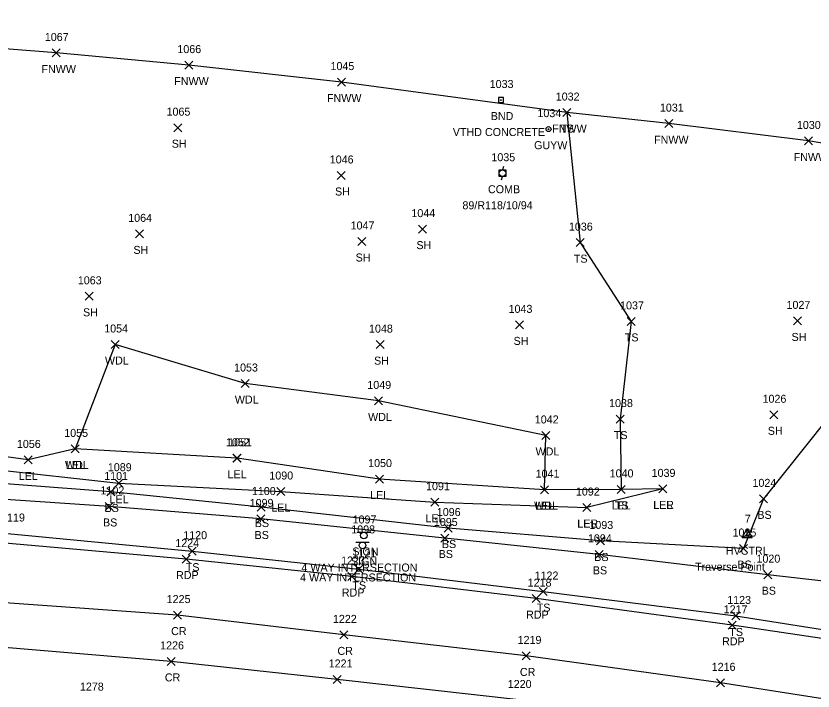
# Model space of a CAD drawing. Extents: x 1629176 to 1637209, y 606063 to 610167.
# Drawn here: x 1629364 to 1629563.1, y 607047.2 to 607215.9 of the extents above; entities that cross this region are included whole.
import ezdxf

# ---------------------------------------------------------------- set-up
doc = ezdxf.new("R2010")
doc.units = 0
for name, color, linetype in [('C_A', 7, 'Continuous'), ('C_C', 7, 'Continuous'), ('C_I', 7, 'Continuous'), ('CPSM', 7, 'Continuous'), ('L_A', 7, 'Continuous'), ('L_I', 7, 'Continuous'), ('L_TIC', 7, 'Continuous'), ('LARO', 7, 'Continuous'), ('LAWA', 7, 'Continuous'), ('LELB', 7, 'Continuous'), ('LFNC', 7, 'Continuous'), ('M_A', 7, 'Continuous'), ('M_C', 7, 'Continuous'), ('M_I', 7, 'Continuous'), ('MHBP', 7, 'Continuous'), ('P_A', 7, 'Continuous'), ('P_I', 7, 'Continuous'), ('P_TIC', 7, 'Continuous'), ('PET', 7, 'Continuous'), ('PRC', 7, 'Continuous'), ('S_A', 7, 'Continuous'), ('S_C', 7, 'Continuous'), ('S_I', 7, 'Continuous'), ('SSGN', 7, 'Continuous'), ('U_A', 7, 'Continuous'), ('U_C', 7, 'Continuous'), ('U_I', 7, 'Continuous'), ('UP', 7, 'Continuous'), ('UPGW', 7, 'Continuous')]:
    doc.layers.add(name, color=color, linetype=linetype)

msp = doc.modelspace()

# ---------------------------------------------------------------- linework, layer by layer
at = {"layer": 'CPSM'}
for p, q in [((1629545.35, 607085.58), (1629546.6, 607087.75)), ((1629545.35, 607085.58), (1629546.6, 607086.3)), ((1629547.85, 607085.58), (1629546.6, 607087.75)), ((1629546.6, 607086.3), (1629546.6, 607087.75)), ((1629546.6, 607086.3), (1629546.6, 607086.3)), ((1629546.6, 607086.3), (1629547.85, 607085.58)), ((1629545.35, 607085.58), (1629547.85, 607085.58))]:
    msp.add_line(p, q, dxfattribs=at)
at = {"layer": 'L_TIC'}
for points in [[(1629373.06, 607205.64), (1629375.06, 607207.64)], [(1629375.06, 607205.64), (1629373.06, 607207.64)], [(1629406.21, 607202.61), (1629408.21, 607204.61)], [(1629408.21, 607202.61), (1629406.21, 607204.61)], [(1629444.35, 607198.37), (1629446.35, 607200.37)], [(1629446.35, 607198.37), (1629444.35, 607200.37)], [(1629500.6, 607190.75), (1629502.6, 607192.75)], [(1629502.6, 607190.75), (1629500.6, 607192.75)], [(1629500.6, 607190.75), (1629502.6, 607192.75)], [(1629502.6, 607190.75), (1629500.6, 607192.75)], [(1629526.04, 607187.99), (1629528.04, 607189.99)], [(1629528.04, 607187.99), (1629526.04, 607189.99)], [(1629403.46, 607186.98), (1629405.46, 607188.98)], [(1629405.46, 607186.98), (1629403.46, 607188.98)], [(1629560.91, 607183.66), (1629562.91, 607185.66)], [(1629562.91, 607183.66), (1629560.91, 607185.66)], [(1629444.22, 607175.04), (1629446.22, 607177.04)], [(1629446.22, 607175.04), (1629444.22, 607177.04)], [(1629393.88, 607160.45), (1629395.88, 607162.45)], [(1629395.88, 607160.45), (1629393.88, 607162.45)], [(1629464.56, 607161.64), (1629466.56, 607163.64)], [(1629466.56, 607161.64), (1629464.56, 607163.64)], [(1629449.37, 607158.55), (1629451.37, 607160.55)], [(1629451.37, 607158.55), (1629449.37, 607160.55)], [(1629503.94, 607158.27), (1629505.94, 607160.27)], [(1629505.94, 607158.27), (1629503.94, 607160.27)], [(1629381.3, 607144.86), (1629383.3, 607146.86)], [(1629383.3, 607144.86), (1629381.3, 607146.86)], [(1629516.67, 607138.59), (1629518.67, 607140.59)], [(1629518.67, 607138.59), (1629516.67, 607140.59)], [(1629558.23, 607138.71), (1629560.23, 607140.71)], [(1629560.23, 607138.71), (1629558.23, 607140.71)], [(1629488.82, 607137.72), (1629490.82, 607139.72)], [(1629490.82, 607137.72), (1629488.82, 607139.72)], [(1629387.84, 607132.82), (1629389.84, 607134.82)], [(1629389.84, 607132.82), (1629387.84, 607134.82)], [(1629453.97, 607132.79), (1629455.97, 607134.79)], [(1629455.97, 607132.79), (1629453.97, 607134.79)], [(1629420.28, 607123.07), (1629422.28, 607125.07)], [(1629422.28, 607123.07), (1629420.28, 607125.07)], [(1629453.55, 607118.72), (1629455.55, 607120.72)], [(1629455.55, 607118.72), (1629453.55, 607120.72)], [(1629513.92, 607114.19), (1629515.92, 607116.19)], [(1629515.92, 607114.19), (1629513.92, 607116.19)], [(1629552.3, 607115.26), (1629554.3, 607117.26)], [(1629554.3, 607115.26), (1629552.3, 607117.26)], [(1629495.37, 607110.1), (1629497.37, 607112.1)], [(1629497.37, 607110.1), (1629495.37, 607112.1)], [(1629377.86, 607106.73), (1629379.86, 607108.73)], [(1629379.86, 607106.73), (1629377.86, 607108.73)], [(1629377.86, 607106.73), (1629379.86, 607108.73)], [(1629379.86, 607106.73), (1629377.86, 607108.73)], [(1629366.09, 607103.98), (1629368.09, 607105.98)], [(1629368.09, 607103.98), (1629366.09, 607105.98)], [(1629418.23, 607104.4), (1629420.23, 607106.4)], [(1629420.23, 607104.4), (1629418.23, 607106.4)], [(1629418.24, 607104.4), (1629420.24, 607106.4)], [(1629420.24, 607104.4), (1629418.24, 607106.4)], [(1629388.76, 607098.17), (1629390.76, 607100.17)], [(1629390.76, 607098.17), (1629388.76, 607100.17)], [(1629453.84, 607099.2), (1629455.84, 607101.2)], [(1629455.84, 607099.2), (1629453.84, 607101.2)], [(1629429.17, 607096.09), (1629431.17, 607098.09)], [(1629431.17, 607096.09), (1629429.17, 607098.09)], [(1629495.01, 607096.55), (1629497.01, 607098.55)], [(1629497.01, 607096.55), (1629495.01, 607098.55)], [(1629495.01, 607096.55), (1629497.01, 607098.55)], [(1629497.01, 607096.55), (1629495.01, 607098.55)], [(1629514.16, 607096.62), (1629516.16, 607098.62)], [(1629516.16, 607096.62), (1629514.16, 607098.62)], [(1629514.16, 607096.62), (1629516.16, 607098.62)], [(1629516.16, 607096.62), (1629514.16, 607098.62)], [(1629524.56, 607096.75), (1629526.56, 607098.75)], [(1629526.56, 607096.75), (1629524.56, 607098.75)], [(1629524.56, 607096.75), (1629526.56, 607098.75)], [(1629526.56, 607096.75), (1629524.56, 607098.75)], [(1629386.71, 607095.98), (1629388.71, 607097.98)], [(1629388.71, 607095.98), (1629386.71, 607097.98)], [(1629549.74, 607094.26), (1629551.74, 607096.26)], [(1629551.74, 607094.26), (1629549.74, 607096.26)], [(1629386.34, 607092.37), (1629388.34, 607094.37)], [(1629388.34, 607092.37), (1629386.34, 607094.37)], [(1629424.24, 607092.21), (1629426.24, 607094.21)], [(1629426.24, 607092.21), (1629424.24, 607094.21)], [(1629467.65, 607093.42), (1629469.65, 607095.42)], [(1629469.65, 607093.42), (1629467.65, 607095.42)], [(1629505.63, 607092.09), (1629507.63, 607094.09)], [(1629507.63, 607092.09), (1629505.63, 607094.09)], [(1629505.63, 607092.09), (1629507.63, 607094.09)], [(1629507.63, 607092.09), (1629505.63, 607094.09)], [(1629424.18, 607089.24), (1629426.18, 607091.24)], [(1629426.18, 607089.24), (1629424.18, 607091.24)], [(1629470.96, 607086.97), (1629472.96, 607088.97)], [(1629472.96, 607086.97), (1629470.96, 607088.97)], [(1629470.16, 607084.48), (1629472.16, 607086.48)], [(1629472.16, 607084.48), (1629470.16, 607086.48)], [(1629509.01, 607083.74), (1629511.01, 607085.74)], [(1629511.01, 607083.74), (1629509.01, 607085.74)], [(1629407.03, 607081.19), (1629409.03, 607083.19)], [(1629409.03, 607081.19), (1629407.03, 607083.19)], [(1629508.64, 607080.4), (1629510.64, 607082.4)], [(1629510.64, 607080.4), (1629508.64, 607082.4)], [(1629544.75, 607081.85), (1629546.75, 607083.85)], [(1629546.75, 607081.85), (1629544.75, 607083.85)], [(1629448.64, 607076.67), (1629450.64, 607078.67)], [(1629450.64, 607076.67), (1629448.64, 607078.67)], [(1629550.82, 607075.32), (1629552.82, 607077.32)], [(1629552.82, 607075.32), (1629550.82, 607077.32)], [(1629494.68, 607071.1), (1629496.68, 607073.1)], [(1629496.68, 607071.1), (1629494.68, 607073.1)], [(1629542.77, 607065.01), (1629544.77, 607067.01)], [(1629544.77, 607065.01), (1629542.77, 607067.01)]]:
    msp.add_lwpolyline(points, dxfattribs=at)
at = {"layer": 'LARO'}
for points in [[(1629525.56, 607097.75), (1629515.16, 607097.62), (1629496.01, 607097.55), (1629454.84, 607100.2), (1629419.24, 607105.4), (1629419.23, 607105.4), (1629378.86, 607107.73), (1629367.09, 607104.98), (1629352.35, 607107.03), (1629331.53, 607114.27), (1629312.1, 607112.36), (1629284.4, 607117.27), (1629264.96, 607112.44), (1629237.03, 607114.71), (1629236.02, 607111.12), (1629264.43, 607110.11), (1629291.77, 607108.71), (1629324.64, 607106.29), (1629358.13, 607102.7), (1629389.76, 607099.17), (1629430.17, 607097.09), (1629468.65, 607094.42), (1629506.63, 607093.09)], [(1629525.56, 607097.75), (1629506.63, 607093.09)]]:
    msp.add_lwpolyline(points, dxfattribs=at)
at = {"layer": 'LAWA'}
msp.add_lwpolyline([(1629496.01, 607097.55), (1629496.37, 607111.1), (1629454.55, 607119.72), (1629421.28, 607124.07), (1629388.84, 607133.82), (1629378.86, 607107.73)], dxfattribs=at)
at = {"layer": 'LELB'}
for points in [[(1629501.6, 607191.75), (1629504.94, 607159.27), (1629517.67, 607139.59), (1629514.92, 607115.19), (1629515.16, 607097.62)], [(1629624.92, 607174.61), (1629622.69, 607143.68), (1629611.35, 607114.32), (1629581.53, 607116.51), (1629566.42, 607115.03), (1629550.74, 607095.26), (1629545.75, 607082.85), (1629510.01, 607084.74), (1629471.96, 607087.97), (1629425.24, 607093.21), (1629387.71, 607096.98), (1629341.68, 607100.48), (1629296.79, 607103.99), (1629252.13, 607105.67), (1629240.26, 607107.21), (1629209.02, 607107.58), (1629183.53, 607109.94)], [(1629683.15, 607057.43), (1629646, 607061.54), (1629600.81, 607070.68), (1629551.82, 607076.32), (1629509.64, 607081.4), (1629471.16, 607085.48), (1629425.18, 607090.24), (1629387.34, 607093.37), (1629341.71, 607096.43), (1629295.02, 607099.94), (1629251.22, 607103.28), (1629239.88, 607103.86), (1629208.74, 607106), (1629183.2, 607107.98)], [(1629182.81, 607095.71), (1629228.31, 607094.18), (1629271.2, 607092.37), (1629318.24, 607089.8), (1629361.89, 607086.6), (1629408.03, 607082.19), (1629449.64, 607077.67), (1629495.68, 607072.1), (1629543.77, 607066.01), (1629589.78, 607058.79)]]:
    msp.add_lwpolyline(points, dxfattribs=at)
at = {"layer": 'LFNC'}
msp.add_lwpolyline([(1629584.57, 607180.8), (1629561.91, 607184.66), (1629527.04, 607188.99), (1629501.6, 607191.75), (1629445.35, 607199.37), (1629407.21, 607203.61), (1629374.06, 607206.64), (1629338.82, 607209.46), (1629316.51, 607210.37), (1629282.73, 607212.04), (1629269.2, 607213.11), (1629248.99, 607214.08), (1629210.8, 607215.89), (1629190.17, 607214.66)], dxfattribs=at)
at = {"layer": 'MHBP'}
for p, q in [((1629485.76, 607195.54), (1629484.51, 607195.54)), ((1629484.51, 607195.54), (1629484.51, 607194.29)), ((1629485.76, 607195.54), (1629484.51, 607195.54)), ((1629484.51, 607195.54), (1629484.51, 607194.29)), ((1629485.76, 607194.29), (1629485.76, 607195.54)), ((1629485.76, 607194.29), (1629485.76, 607195.54)), ((1629484.51, 607194.29), (1629485.76, 607194.29)), ((1629484.51, 607194.29), (1629485.76, 607194.29))]:
    msp.add_line(p, q, dxfattribs=at)
msp.add_circle((1629485.11, 607194.88), 0.0833, dxfattribs=at)
at = {"layer": 'P_TIC'}
for points in [[(1629405.53, 607079.22), (1629407.53, 607081.22)], [(1629407.53, 607079.22), (1629405.53, 607081.22)], [(1629446.94, 607074.86), (1629448.94, 607076.86)], [(1629448.94, 607074.86), (1629446.94, 607076.86)], [(1629492.94, 607069.34), (1629494.94, 607071.34)], [(1629494.94, 607069.34), (1629492.94, 607071.34)], [(1629403.36, 607065.23), (1629405.36, 607067.23)], [(1629405.36, 607065.23), (1629403.36, 607067.23)], [(1629541.89, 607062.67), (1629543.89, 607064.67)], [(1629543.89, 607062.67), (1629541.89, 607064.67)], [(1629444.88, 607060.28), (1629446.88, 607062.28)], [(1629446.88, 607060.28), (1629444.88, 607062.28)], [(1629490.45, 607055.02), (1629492.45, 607057.02)], [(1629492.45, 607055.02), (1629490.45, 607057.02)], [(1629401.79, 607053.66), (1629403.79, 607055.66)], [(1629403.79, 607053.66), (1629401.79, 607055.66)], [(1629443.26, 607049.14), (1629445.26, 607051.14)], [(1629445.26, 607049.14), (1629443.26, 607051.14)], [(1629538.96, 607048.3), (1629540.96, 607050.3)], [(1629540.96, 607048.3), (1629538.96, 607050.3)]]:
    msp.add_lwpolyline(points, dxfattribs=at)
at = {"layer": 'PET'}
msp.add_lwpolyline([(1630115.59, 606918.47), (1630070.26, 606934.37), (1630047.19, 606942.61), (1630027.81, 606949.5), (1629999.64, 606958.79), (1629963.88, 606969.73), (1629916.37, 606983.66), (1629883.8, 606991.87), (1629841.7, 607003.38), (1629794.53, 607014.94), (1629751.13, 607024.85), (1629703.98, 607035.26), (1629666.74, 607043.02), (1629621.43, 607051.04), (1629588.28, 607056.93), (1629542.89, 607063.67), (1629493.94, 607070.34), (1629447.94, 607075.86), (1629406.53, 607080.22), (1629360.37, 607084.28), (1629316.73, 607087.48), (1629269.81, 607090.12), (1629227.29, 607092.24), (1629182.92, 607093.47)], dxfattribs=at)
at = {"layer": 'PRC'}
for points in [[(1630110.18, 606905.77), (1630065.36, 606921.68), (1630022.36, 606935.68), (1629994.71, 606945.36), (1629959.54, 606955.86), (1629913.54, 606969.37), (1629877.41, 606979.26), (1629837.69, 606989.99), (1629791.63, 607000.82), (1629746.42, 607011.44), (1629699.59, 607021.37), (1629664.04, 607028.34), (1629619.43, 607036.79), (1629585.72, 607042.18), (1629539.96, 607049.3), (1629491.45, 607056.02), (1629445.88, 607061.28), (1629404.36, 607066.23), (1629358.89, 607069.49), (1629314.63, 607073.29), (1629269.37, 607075.36), (1629226.58, 607077.32), (1629182.35, 607078.58)], [(1630105.99, 606894.95), (1630061.18, 606910.94), (1630017.61, 606925.74), (1629991.01, 606934.32), (1629955.3, 606944.84), (1629910.77, 606959.12), (1629874.52, 606969.06), (1629834.93, 606979.4), (1629788.74, 606990.13), (1629743.3, 607000.68), (1629697.98, 607010.33), (1629662.17, 607017.56), (1629618.2, 607025.81), (1629583.59, 607031.56), (1629540.4, 607037.95), (1629489.63, 607045.02), (1629444.26, 607050.14), (1629402.79, 607054.66), (1629359.1, 607058.26), (1629313.06, 607061.88), (1629268.47, 607063.97), (1629226.23, 607065.89), (1629182.22, 607066.96)]]:
    msp.add_lwpolyline(points, dxfattribs=at)
at = {"layer": 'SSGN'}
for p, q in [((1629449.24, 607086.97), (1629452.58, 607086.97)), ((1629450.89, 607086.13), (1629450.89, 607086.13)), ((1629448.92, 607084.48), (1629452.25, 607084.48)), ((1629450.56, 607083.65), (1629450.56, 607083.65))]:
    msp.add_line(p, q, dxfattribs=at)
for centre in [(1629450.89, 607086.13), (1629450.56, 607083.65)]:
    msp.add_circle(centre, 0.833, dxfattribs=at)
at = {"layer": 'UP'}
for p, q in [((1629485.78, 607178.27), (1629485.53, 607177.43)), ((1629484.69, 607175.77), (1629484.69, 607177.43)), ((1629484.69, 607177.43), (1629486.36, 607177.43)), ((1629486.36, 607175.77), (1629484.69, 607175.77)), ((1629485.28, 607174.93), (1629485.53, 607175.77)), ((1629485.53, 607176.6), (1629485.53, 607176.6)), ((1629486.36, 607177.43), (1629486.36, 607175.77))]:
    msp.add_line(p, q, dxfattribs=at)
msp.add_circle((1629485.53, 607176.6), 0.833, dxfattribs=at)
at = {"layer": 'UPGW'}
for radius in [0.625, 0.0833]:
    msp.add_circle((1629497.03, 607187.61), radius, dxfattribs=at)

# ---------------------------------------------------------------- texts
at = {"layer": 'C_A'}
msp.add_text('HVCTRL', height=2, dxfattribs=at).set_placement((1629541.3, 607081.3))
at = {"layer": 'C_C'}
msp.add_text('Traverse Point', height=2, dxfattribs=at).set_placement((1629533.65, 607077.3))
at = {"layer": 'C_I'}
msp.add_text('7', height=2, dxfattribs=at).set_placement((1629546.04, 607089.3))
at = {"layer": 'L_A'}
for s, p in [('FNWW', (1629370.41, 607201.64)), ('FNWW', (1629403.56, 607198.61)), ('FNWW', (1629441.7, 607194.37)), ('FNWW', (1629497.95, 607186.75)), ('TS', (1629500.01, 607186.75)), ('FNWW', (1629523.39, 607183.99)), ('SH', (1629402.95, 607182.98)), ('FNWW', (1629558.25, 607179.66)), ('SH', (1629443.71, 607171.04)), ('SH', (1629393.37, 607156.45)), ('SH', (1629464.04, 607157.64)), ('SH', (1629448.86, 607154.55)), ('TS', (1629503.35, 607154.27)), ('SH', (1629380.78, 607140.86)), ('TS', (1629516.08, 607134.59)), ('SH', (1629557.72, 607134.71)), ('SH', (1629488.31, 607133.72)), ('WDL', (1629386.26, 607128.82)), ('SH', (1629453.46, 607128.79)), ('WDL', (1629418.69, 607119.07)), ('WDL', (1629451.97, 607114.72)), ('TS', (1629513.33, 607110.19)), ('SH', (1629551.79, 607111.26)), ('WDL', (1629493.79, 607106.1)), ('WDL', (1629376.27, 607102.73)), ('LEL', (1629376.5, 607102.73)), ('LEL', (1629364.73, 607099.98)), ('LEL', (1629416.87, 607100.4)), ('LEL', (1629416.88, 607100.4)), ('LEL', (1629387.4, 607094.17)), ('LEL', (1629452.47, 607095.2)), ('LEL', (1629427.8, 607092.09)), ('WDL', (1629493.43, 607092.55)), ('LEL', (1629493.65, 607092.55)), ('LEL', (1629512.8, 607092.62)), ('TS', (1629513.57, 607092.62)), ('LER', (1629523.14, 607092.75)), ('LEL', (1629523.2, 607092.75)), ('BS', (1629386.15, 607091.98)), ('BS', (1629549.18, 607090.26)), ('BS', (1629385.78, 607088.37)), ('BS', (1629423.68, 607088.21)), ('LEL', (1629466.29, 607089.42)), ('LER', (1629504.21, 607088.09)), ('LEL', (1629504.27, 607088.09)), ('BS', (1629423.63, 607085.24)), ('BS', (1629470.4, 607082.97)), ('BS', (1629469.6, 607080.48)), ('BS', (1629508.45, 607079.74)), ('TS', (1629406.44, 607077.19)), ('BS', (1629508.09, 607076.4)), ('BS', (1629544.2, 607077.85)), ('TS', (1629448.05, 607072.67)), ('BS', (1629550.26, 607071.32)), ('TS', (1629494.09, 607067.1)), ('TS', (1629542.18, 607061.01))]:
    msp.add_text(s, height=2, dxfattribs=at).set_placement(p)
at = {"layer": 'L_I'}
for s, p in [('1067', (1629371.24, 607209.64)), ('1066', (1629404.34, 607206.61)), ('1045', (1629442.58, 607202.37)), ('1032', (1629498.83, 607194.75)), ('1032', (1629498.83, 607194.75)), ('1031', (1629524.84, 607191.99)), ('1065', (1629401.64, 607190.98)), ('1030', (1629559.05, 607187.66)), ('1046', (1629442.4, 607179.04)), ('1044', (1629462.78, 607165.64)), ('1064', (1629392.07, 607164.45)), ('1047', (1629447.6, 607162.55)), ('1036', (1629502.12, 607162.27)), ('1063', (1629379.48, 607148.86)), ('1037', (1629514.9, 607142.59)), ('1027', (1629556.46, 607142.71)), ('1043', (1629487.05, 607141.72)), ('1054', (1629386.07, 607136.82)), ('1048', (1629452.2, 607136.79)), ('1053', (1629418.51, 607127.07)), ('1049', (1629451.78, 607122.72)), ('1038', (1629512.15, 607118.19)), ('1026', (1629550.47, 607119.26)), ('1042', (1629493.6, 607114.1)), ('1055', (1629376.09, 607110.73)), ('1055', (1629376.09, 607110.73)), ('1056', (1629364.27, 607107.98)), ('1052', (1629416.46, 607108.4)), ('1051', (1629417.03, 607108.4)), ('1089', (1629386.98, 607102.17)), ('1050', (1629451.98, 607103.2)), ('1101', (1629386.07, 607099.98)), ('1090', (1629427.31, 607100.09)), ('1041', (1629493.81, 607100.55)), ('1041', (1629493.81, 607100.55)), ('1040', (1629512.3, 607100.62)), ('1040', (1629512.3, 607100.62)), ('1039', (1629522.78, 607100.75)), ('1039', (1629522.78, 607100.75)), ('1024', (1629547.96, 607098.26)), ('1102', (1629385.14, 607096.37)), ('1100', (1629422.95, 607096.21)), ('1091', (1629466.44, 607097.42)), ('1092', (1629503.86, 607096.09)), ('1092', (1629503.86, 607096.09)), ('1099', (1629422.4, 607093.24)), ('1096', (1629469.13, 607090.97)), ('1119', (1629360.32, 607089.6)), ('1095', (1629468.39, 607088.48)), ('1093', (1629507.23, 607087.74)), ('1120', (1629405.81, 607085.19)), ('1094', (1629506.87, 607084.4)), ('1025', (1629542.98, 607085.85)), ('1121', (1629448.08, 607080.67)), ('1020', (1629548.96, 607079.32)), ('1122', (1629493.55, 607075.1)), ('1123', (1629541.65, 607069.01))]:
    msp.add_text(s, height=2, dxfattribs=at).set_placement(p)
at = {"layer": 'M_A'}
msp.add_text('BND', height=2, dxfattribs=at).set_placement((1629482.6, 607189.89))
at = {"layer": 'M_C'}
msp.add_text('VTHD CONCRETE', height=2, dxfattribs=at).set_placement((1629473.13, 607185.89))
at = {"layer": 'M_I'}
msp.add_text('1033', height=2, dxfattribs=at).set_placement((1629482.34, 607197.89))
at = {"layer": 'P_A'}
for s, p in [('RDP', (1629404.01, 607075.22)), ('RDP', (1629445.42, 607070.86)), ('RDP', (1629491.43, 607065.34)), ('CR', (1629402.79, 607061.23)), ('RDP', (1629540.38, 607058.67)), ('CR', (1629444.32, 607056.28)), ('CR', (1629489.88, 607051.02)), ('CR', (1629401.22, 607049.66))]:
    msp.add_text(s, height=2, dxfattribs=at).set_placement(p)
at = {"layer": 'P_I'}
for s, p in [('1224', (1629403.83, 607083.22)), ('1223', (1629445.24, 607078.86)), ('1218', (1629491.82, 607073.34)), ('1225', (1629401.67, 607069.23)), ('1217', (1629540.76, 607066.67)), ('1222', (1629443.19, 607064.28)), ('1219', (1629489.31, 607059.02)), ('1226', (1629400.04, 607057.66)), ('1221', (1629442.13, 607053.14)), ('1216', (1629537.78, 607052.3)), ('1278', (1629380.01, 607047.36)), ('1220', (1629486.85, 607048.02))]:
    msp.add_text(s, height=2, dxfattribs=at).set_placement(p)
at = {"layer": 'S_A'}
for p in [(1629448.03, 607081.11), (1629447.7, 607078.63)]:
    msp.add_text('SIGN', height=2, dxfattribs=at).set_placement(p)
at = {"layer": 'S_C'}
for p in [(1629435.32, 607077.11), (1629434.99, 607074.63)]:
    msp.add_text('4 WAY INTERSECTION', height=2, dxfattribs=at).set_placement(p)
at = {"layer": 'S_I'}
for s, p in [('1097', (1629448.1, 607089.11)), ('1098', (1629447.77, 607086.63))]:
    msp.add_text(s, height=2, dxfattribs=at).set_placement(p)
at = {"layer": 'U_A'}
for s, p in [('GUYW', (1629493.42, 607182.61)), ('COMB', (1629481.91, 607171.6))]:
    msp.add_text(s, height=2, dxfattribs=at).set_placement(p)
at = {"layer": 'U_C'}
msp.add_text('89/R118/10/94', height=2, dxfattribs=at).set_placement((1629475.53, 607167.6))
at = {"layer": 'U_I'}
for s, p in [('1034', (1629494.26, 607190.61)), ('1035', (1629482.76, 607179.6))]:
    msp.add_text(s, height=2, dxfattribs=at).set_placement(p)

doc.saveas('drawing.dxf')
